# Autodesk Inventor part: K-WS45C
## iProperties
Created: 2009-07
Part Number: K-WS45C
Document SubType Name: Modeling
Designer: TB
Mass: 253.373 g
Surface Area: 400.547 cm^2
Volume: 253.373 cm^3
Density: 1 g/cm^3
Author: TB
